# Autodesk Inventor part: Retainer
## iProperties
Shininess: 20.0
Length Units: 11269
Angle Units: 11279
Time Units: 11290
Mass Units: 11283
Length Display Precision: 3
Angle Display Precision: 2
Created: 2002-01
Part Number: Retainer
Document SubType Name: Modeling
Designer: ***
Density: 0.0
Volumn: 0.0
Area: 0.0
PropertySet Name: Model Information
Control State: 0
Master: False
Checked Out: False
Author: ***
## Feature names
1. Extrusion1
